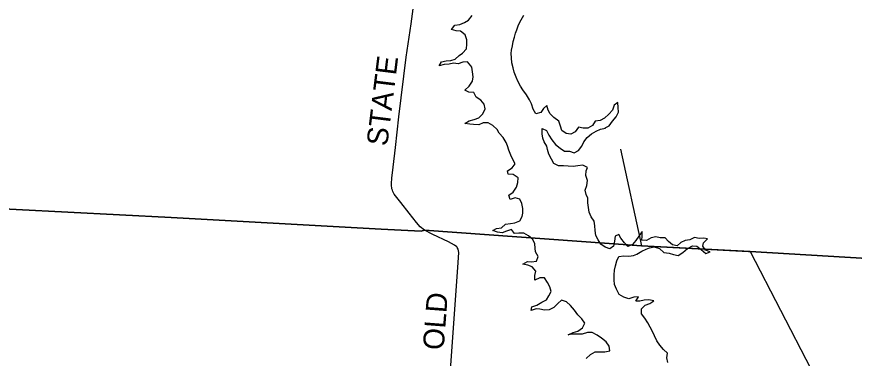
# Model space of a CAD drawing. Extents: x 1674899 to 2057726, y 653888 to 988278.
# Drawn here: x 1833082 to 1845104, y 831243 to 836141 of the extents above; entities that cross this region are included whole.
import ezdxf

# ---------------------------------------------------------------- set-up
doc = ezdxf.new("R2010")
doc.units = 0
for name, color, linetype in [('GM_X_County_Road', 7, 'Continuous'), ('GM_X_County_Road_Text', 7, 'Continuous'), ('GM_X_Major_Lake', 7, 'Continuous'), ('GM_X_Township', 7, 'Continuous'), ('GM_X_Township_ROW', 7, 'Continuous')]:
    doc.layers.add(name, color=color, linetype=linetype)

msp = doc.modelspace()

# ---------------------------------------------------------------- linework, layer by layer
at = {"layer": 'GM_X_County_Road'}
for points in [[(1838934, 833082), (1838875, 833130), (1838820, 833190), (1838713, 833324), (1838593, 833477), (1838502, 833596), (1838490, 833616), (1838481, 833634), (1838474, 833652), (1838468, 833671), (1838464, 833691), (1838461, 833711), (1838461, 833751), (1838466, 833825), (1838487, 833985), (1838519, 834265), (1838567, 834705), (1838674, 835560), (1838743, 836040), (1838773, 836253)], [(1839405, 832831), (1839399, 832841), (1839368, 832866), (1839279, 832914), (1839055, 833020), (1838934, 833082)], [(1839090, 828131), (1839096, 828247), (1839106, 828377), (1839155, 829045), (1839297, 830940), (1839419, 832616), (1839427, 832761), (1839419, 832807), (1839405, 832831)]]:
    msp.add_lwpolyline(points, dxfattribs=at)
at = {"layer": 'GM_X_Major_Lake'}
for points in [[(1839616, 835418), (1839602, 835438), (1839552, 835494), (1839484, 835488), (1839418, 835464), (1839350, 835475), (1839290, 835461), (1839218, 835457), (1839148, 835435), (1839180, 835495), (1839244, 835507), (1839314, 835515), (1839376, 835531), (1839431, 835584), (1839481, 835620), (1839537, 835680), (1839543, 835748), (1839545, 835812), (1839520, 835880), (1839452, 835933), (1839392, 835941), (1839322, 835959), (1839370, 836023), (1839440, 836031), (1839508, 836059), (1839568, 836094), (1839620, 836158)], [(1841533, 834542), (1841527, 834548), (1841586, 834576), (1841632, 834642), (1841686, 834708), (1841720, 834772), (1841716, 834842), (1841709, 834910), (1841656, 834872), (1841634, 834802), (1841580, 834744), (1841520, 834688), (1841456, 834652), (1841386, 834645), (1841348, 834583), (1841278, 834543), (1841214, 834543), (1841146, 834559), (1841100, 834492), (1841038, 834458), (1840970, 834466), (1840906, 834510), (1840888, 834574), (1840862, 834645), (1840791, 834695), (1840737, 834751), (1840711, 834801), (1840691, 834869), (1840641, 834827), (1840603, 834770), (1840535, 834748), (1840497, 834814), (1840473, 834890), (1840444, 834952), (1840398, 835019), (1840348, 835093), (1840312, 835147), (1840273, 835215), (1840249, 835277), (1840221, 835345), (1840207, 835408), (1840190, 835480), (1840182, 835550), (1840178, 835612), (1840184, 835662), (1840196, 835726), (1840207, 835786), (1840227, 835850), (1840243, 835904), (1840259, 835956), (1840285, 836024), (1840324, 836096), (1840362, 836166)], [(1840333, 833461), (1840305, 833526), (1840235, 833546), (1840165, 833522), (1840145, 833580), (1840207, 833624), (1840256, 833696), (1840276, 833766), (1840278, 833832), (1840210, 833880), (1840138, 833881), (1840126, 833931), (1840195, 833972), (1840235, 834032), (1840203, 834094), (1840173, 834157), (1840147, 834227), (1840126, 834289), (1840108, 834339), (1840066, 834407), (1840008, 834471), (1839977, 834522), (1839917, 834580), (1839849, 834620), (1839779, 834618), (1839713, 834589), (1839639, 834597), (1839587, 834599), (1839515, 834609), (1839575, 834647), (1839647, 834667), (1839717, 834693), (1839772, 834751), (1839806, 834820), (1839792, 834889), (1839742, 834943), (1839678, 834989), (1839641, 835057), (1839573, 835058), (1839515, 835086), (1839575, 835146), (1839623, 835217), (1839635, 835279), (1839626, 835352), (1839616, 835418)], [(1841327, 833272), (1841301, 833336), (1841288, 833404), (1841280, 833474), (1841278, 833540), (1841258, 833592), (1841241, 833656), (1841265, 833720), (1841273, 833792), (1841253, 833862), (1841256, 833929), (1841274, 833980), (1841206, 834013), (1841138, 834001), (1841070, 833995), (1840998, 833996), (1840932, 834004), (1840860, 834004), (1840794, 834038), (1840759, 834100), (1840719, 834169), (1840703, 834237), (1840689, 834287), (1840655, 834349), (1840632, 834399), (1840622, 834463), (1840624, 834537), (1840686, 834509), (1840722, 834443), (1840761, 834377), (1840817, 834310), (1840883, 834256), (1840947, 834214), (1841017, 834212), (1841085, 834191), (1841147, 834225), (1841195, 834285), (1841221, 834347), (1841271, 834409), (1841331, 834461), (1841401, 834498), (1841463, 834528), (1841533, 834542)], [(1841258, 831240), (1841316, 831298), (1841385, 831336), (1841454, 831334), (1841526, 831335), (1841596, 831351), (1841587, 831417), (1841543, 831479), (1841475, 831532), (1841413, 831572), (1841344, 831610), (1841274, 831611), (1841200, 831587), (1841128, 831589), (1841060, 831589), (1840996, 831580), (1841068, 831611), (1841134, 831633), (1841202, 831679), (1841236, 831745), (1841196, 831807), (1841137, 831867), (1841089, 831933), (1841031, 831998), (1840975, 832054), (1840901, 832076), (1840847, 832030), (1840793, 831973), (1840727, 831937), (1840657, 831931), (1840589, 831949), (1840537, 831952), (1840467, 831926), (1840477, 831978), (1840548, 832006), (1840620, 832049), (1840688, 832079), (1840722, 832137), (1840754, 832201), (1840734, 832269), (1840703, 832329), (1840657, 832397), (1840589, 832394), (1840519, 832364), (1840517, 832428), (1840535, 832492), (1840481, 832552), (1840418, 832580), (1840346, 832591), (1840412, 832633), (1840472, 832628), (1840544, 832636), (1840568, 832704), (1840530, 832770), (1840526, 832822), (1840521, 832884), (1840489, 832948), (1840427, 833001), (1840363, 833037), (1840291, 833035), (1840227, 833034), (1840182, 833092), (1840113, 833064), (1840051, 833044), (1839984, 833050), (1839914, 833077), (1839968, 833105), (1840040, 833114), (1840098, 833164), (1840170, 833178), (1840234, 833184), (1840306, 833213), (1840338, 833275), (1840346, 833325), (1840346, 833391), (1840333, 833461)], [(1842429, 831182), (1842415, 831250), (1842424, 831316), (1842364, 831368), (1842312, 831429), (1842272, 831493), (1842237, 831565), (1842209, 831627), (1842177, 831691), (1842139, 831752), (1842100, 831818), (1842052, 831882), (1842048, 831954), (1842102, 832004), (1842168, 832030), (1842228, 832067), (1842157, 832082), (1842087, 832076), (1842027, 832060), (1841969, 832062), (1842009, 832122), (1841941, 832119), (1841869, 832097), (1841797, 832117), (1841729, 832159), (1841693, 832234), (1841664, 832300), (1841658, 832368), (1841658, 832438), (1841662, 832504), (1841675, 832570), (1841695, 832640), (1841727, 832704), (1841795, 832714), (1841867, 832705), (1841935, 832715), (1841985, 832737), (1842053, 832779), (1842117, 832808), (1842167, 832828), (1842233, 832840), (1842307, 832818), (1842373, 832759), (1842445, 832751), (1842510, 832729), (1842576, 832717), (1842644, 832758), (1842711, 832818), (1842781, 832856), (1842845, 832850), (1842908, 832802), (1842976, 832745), (1843034, 832771), (1842968, 832793), (1842929, 832850), (1842939, 832900), (1842999, 832955), (1842945, 832966), (1842877, 832960), (1842809, 832974), (1842745, 832940), (1842677, 832933), (1842617, 832903), (1842563, 832855), (1842497, 832869), (1842439, 832919), (1842391, 832972), (1842319, 832968), (1842256, 832984), (1842188, 832968), (1842123, 832931), (1842056, 832939), (1842062, 832993), (1842058, 833059), (1842012, 832995), (1841968, 832931), (1841919, 832873), (1841855, 832845), (1841804, 832898), (1841754, 832964), (1841724, 833018), (1841674, 832992), (1841664, 832924), (1841650, 832850), (1841595, 832814), (1841530, 832835), (1841468, 832879), (1841426, 832941), (1841394, 833005), (1841387, 833073), (1841381, 833141), (1841371, 833208), (1841327, 833272)]]:
    msp.add_lwpolyline(points, dxfattribs=at)
at = {"layer": 'GM_X_Township'}
for points in [[(1848030, 848046), (1847065, 833986), (1846971, 832575), (1843609, 832772), (1842052, 832856), (1838934, 833082), (1838887, 833066), (1838313, 833094), (1835297, 833263), (1832327, 833414), (1831529, 833453), (1827748, 833636), (1825602, 833752), (1825545, 833759), (1824931, 833776), (1824840, 833781), (1820873, 833984), (1820182, 834021), (1820274, 835623), (1820357, 837080)], [(1832327, 833414), (1835297, 833263), (1838313, 833094), (1838887, 833066), (1838934, 833082), (1842052, 832856), (1843609, 832772), (1846971, 832575), (1846863, 830918), (1846854, 830870), (1846509, 825988), (1846205, 821378), (1845900, 816686), (1845813, 815443), (1845687, 813540)]]:
    msp.add_lwpolyline(points, dxfattribs=at)
at = {"layer": 'GM_X_Township_ROW'}
for points in [[(1841751, 834242), (1842052, 832856), (1843586, 832773)], [(1843586, 832773), (1843609, 832772), (1844480, 831093)]]:
    msp.add_lwpolyline(points, dxfattribs=at)

# ---------------------------------------------------------------- texts
at = {"layer": 'GM_X_County_Road_Text'}
for s, rotation, p in [('STATE', 82.9842, (1838400, 834277)), ('OLD', 85.6523, (1839209, 831353))]:
    msp.add_text(s, height=300, rotation=rotation, dxfattribs=at).set_placement(p)

doc.saveas('drawing.dxf')
